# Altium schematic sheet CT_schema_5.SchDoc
size 372 x 245 mm
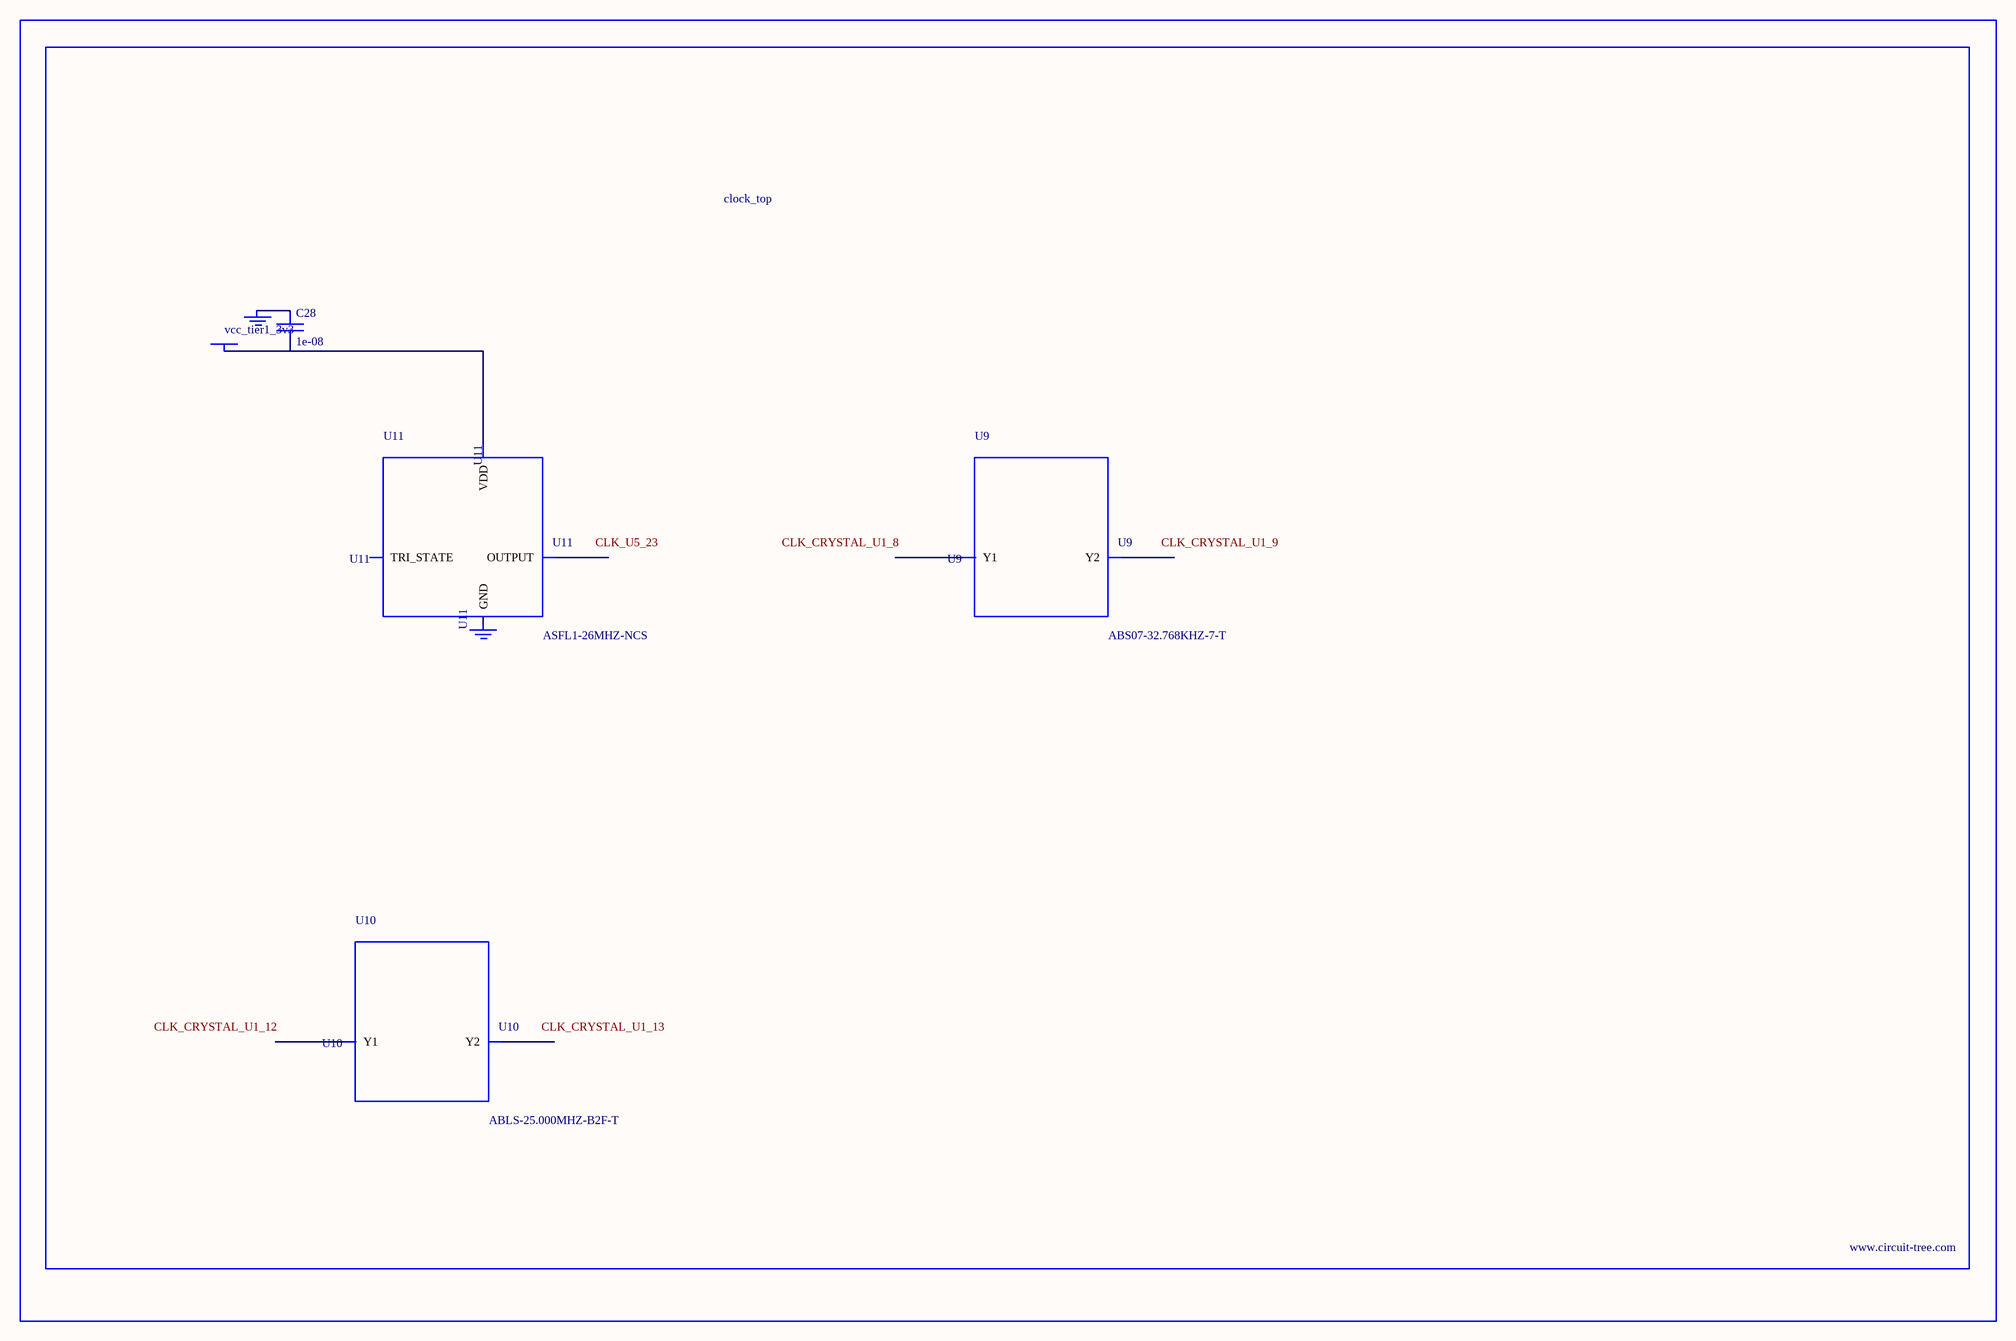
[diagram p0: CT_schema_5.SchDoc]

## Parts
BORDER4  (no value)
C28  1e-08  [C0402]
GND_INSTANCE_4_0  (no value)
GND_INSTANCE_4_1  (no value)
POWER_INSTANCE_4_0  vcc_tier1_3v3
U9  ABS07-32.768KHZ-7-T  [ABS07-32.768KHZ-7-T]
U10  ABLS-25.000MHZ-B2F-T  [ABLS-25.000MHZ-B2F-T]
U11  ASFL1-26MHZ-NCS  [ASFL1]

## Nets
NetC28_1: C28.1 GND_INSTANCE_4_0.0(GND)
NetC28_2: C28.2 POWER_INSTANCE_4_0.0(PWR) U11.4(VDD)

Not connected (* = marked no-connect by the designer): GND_INSTANCE_4_1 0(GND); U9 1(Y1) 2(Y2); U10 1(Y1) 2(Y2); U11 1(TRI_STATE) 2(GND) 3(OUTPUT)

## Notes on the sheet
- Labels drawn without touching a wire or pin: CLK_CRYSTAL_U1_8, CLK_CRYSTAL_U1_9, CLK_CRYSTAL_U1_12, CLK_CRYSTAL_U1_13, CLK_U5_23

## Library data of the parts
BORDER4 = BORDER_PAGE4
C28 = C0402C103K3RAC
GND_INSTANCE_4_0 GND_INSTANCE_4_1 = GND
POWER_INSTANCE_4_0 = PWR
